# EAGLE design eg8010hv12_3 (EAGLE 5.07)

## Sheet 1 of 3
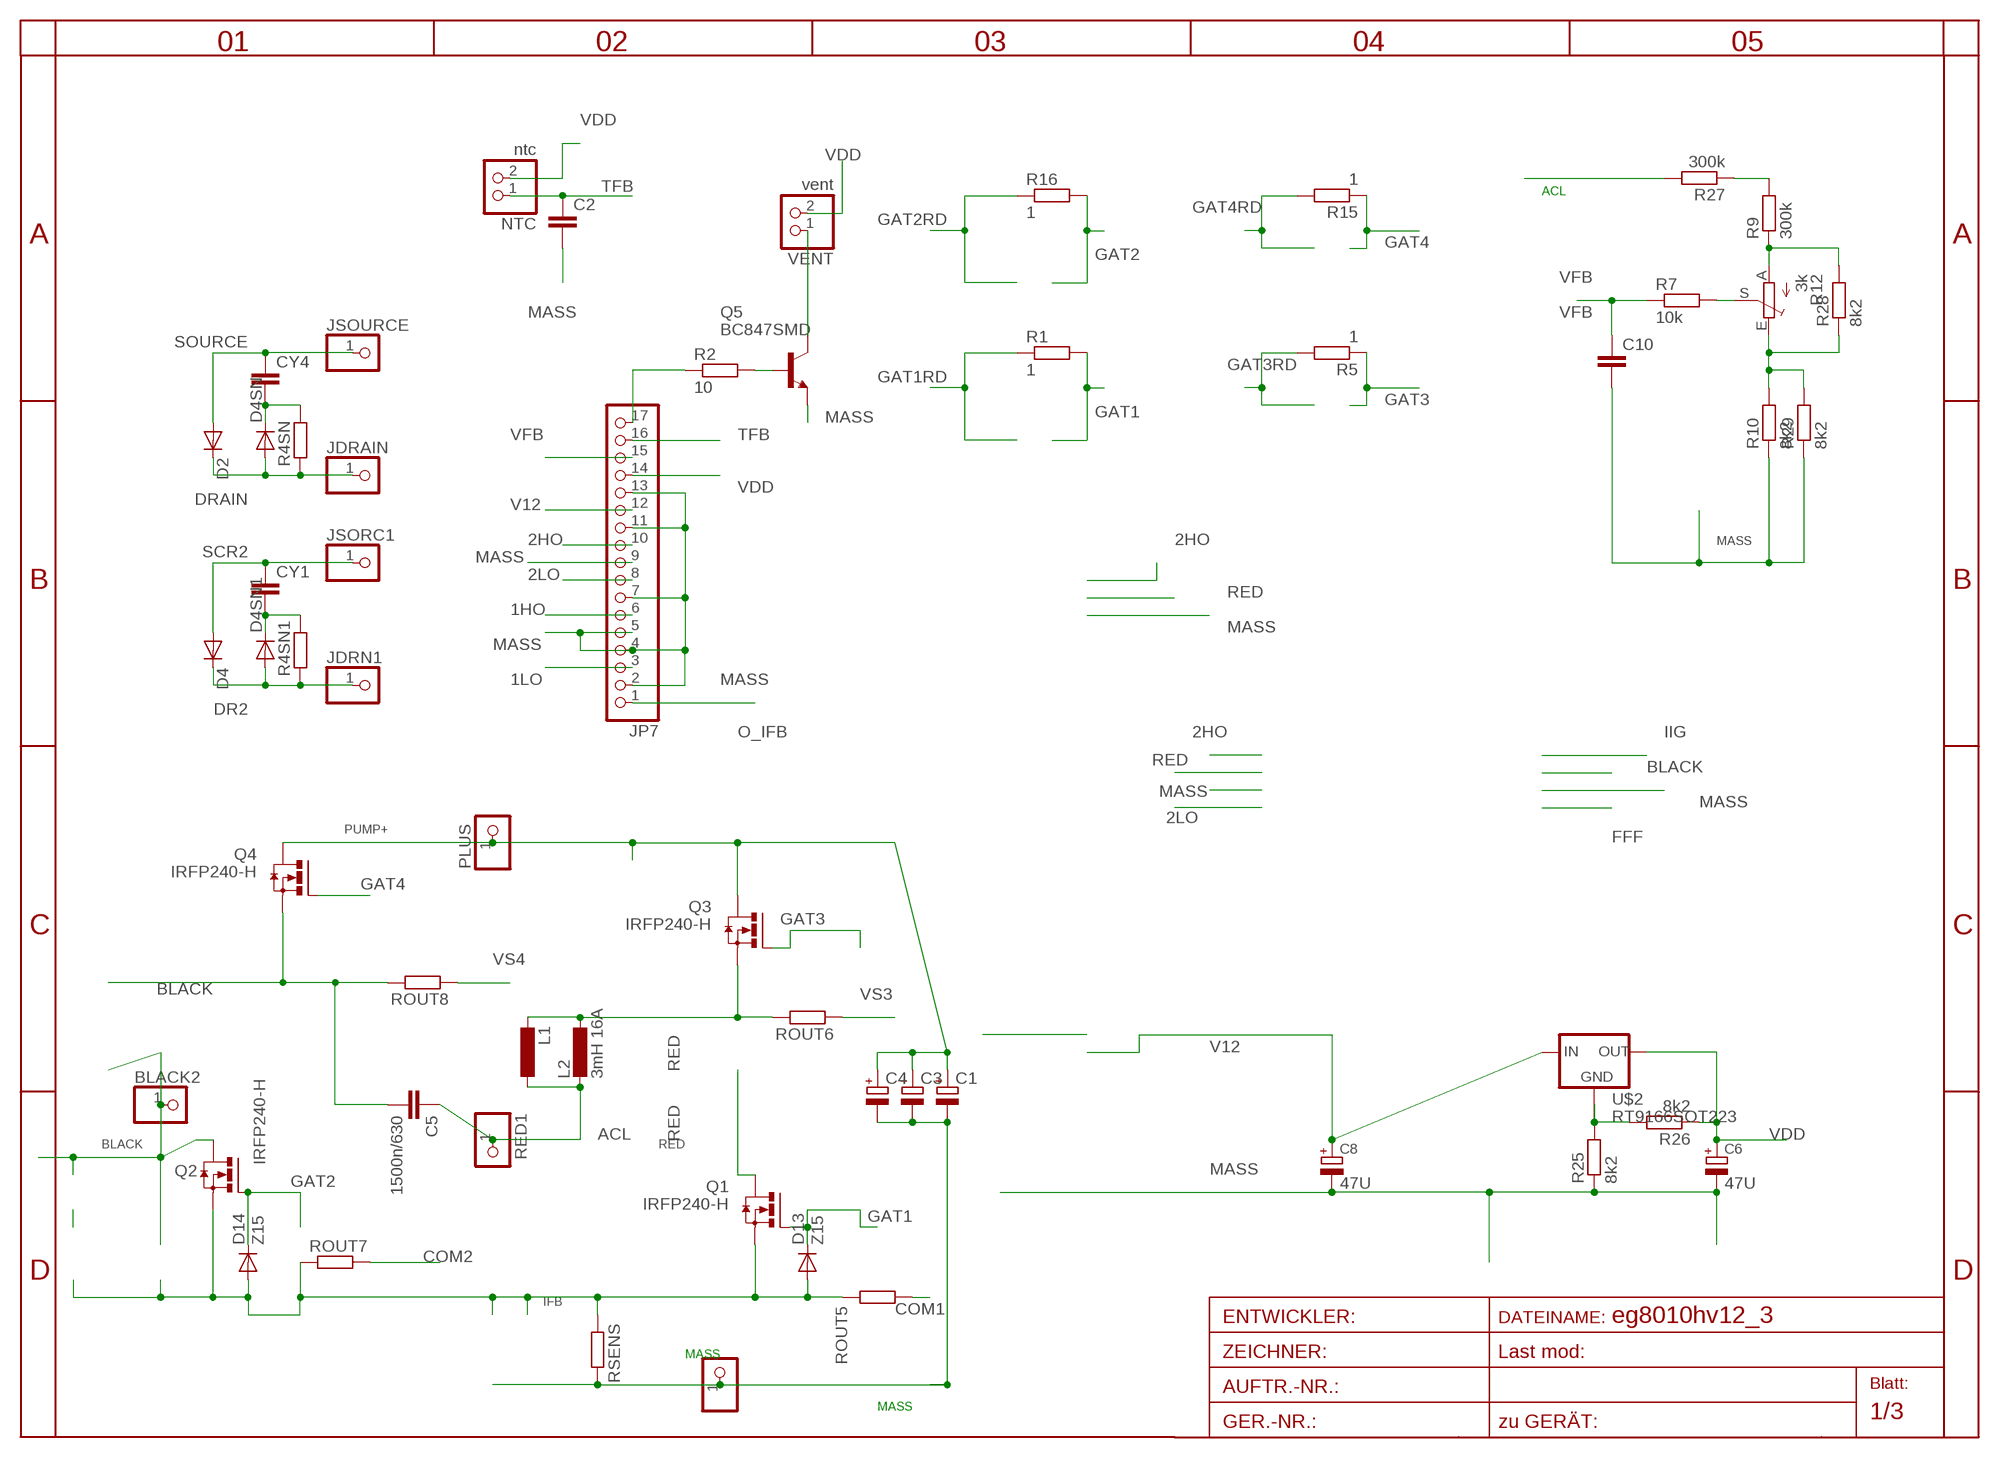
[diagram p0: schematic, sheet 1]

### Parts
BLACK2  PINHD-1X12MM3  [1X2MM3]
C1  CPOL-EUE5-13  [E5-13]
C2  C-EUC1206  [C1206]
C3  CPOL-EUE5-13  [E5-13]
C4  CPOL-EUE5-13  [E5-13]
C5  1500n/630  C-EU275-173X316  [C275-173X316]
C6  47U  CPOL-EUSMCA  [SMC_A]
C8  47U  CPOL-EUSMCA  [SMC_A]
C10  C-EUC0805  [C0805]
CY1  CXXC10B5  [XC10B5]
CY4  CXXC10B5  [XC10B5]
D2  DIODE-SMC  [SMC]
D4  DIODE-SMC  [SMC]
D4SN  DIODE-P1-10  [P1-10]
D4SN1  DIODE-P1-10  [P1-10]
D13  Z15  DIODE-MINIMELF  [MINIMELF]
D14  Z15  DIODE-MINIMELF  [MINIMELF]
JDRAIN  PINHD-1X11MM0  [1X1MM0]
JDRN1  PINHD-1X11MM0  [1X1MM0]
JP7  PINHD-1X17  [1X17]
JSORC1  PINHD-1X11MM0  [1X1MM0]
JSOURCE  PINHD-1X11MM0  [1X1MM0]
L1  L-EU4.13  [0204/13]
L2  3mH 16A  L-EURNG  [RING]
MINUS  PINHD-1X12MM3  [1X2MM3]
NTC  ntc  PINHD-1X2STR  [1X02]
PLUS  PINHD-1X12MM3  [1X2MM3]
Q1  IRFP240-H  [TO247BH]
Q2  IRFP240-H  [TO247BH]
Q3  IRFP240-H  [TO247BH]
Q4  IRFP240-H  [TO247BH]
Q5  BC847SMD  [SOT23]
R1  1  R-EU_R2512  [R2512]
R2  10  R-EU_R0805  [R0805]
R4SN  R-EU_0207/10  [0207/10]
R4SN1  R-EU_0207/10  [0207/10]
R5  1  R-EU_R2512  [R2512]
R7  10k  R-EU_R0805  [R0805]
R9  300k  R-EU_R1206  [R1206]
R10  8k2  R-EU_R0805  [R0805]
R12  3k  TRIM_EU-B64Y  [B64Y]
R15  1  R-EU_R2512  [R2512]
R16  1  R-EU_R2512  [R2512]
R25  8k2  R-EU_R0805  [R0805]
R26  8k2  R-EU_R0805  [R0805]
R27  300k  R-EU_R1206  [R1206]
R28  8k2  R-EU_R1206  [R1206]
R29  8k2  R-EU_R0805  [R0805]
RED1  PINHD-1X12MM3  [1X2MM3]
ROUT5  R-EU_R2512  [R2512]
ROUT6  R-EU_R2512  [R2512]
ROUT7  R-EU_R2512  [R2512]
ROUT8  R-EU_R2512  [R2512]
RSENS  R-EU_WIRE  [WIRE]
U$2  RT9166SOT223  [SOT223]
VENT  vent  PINHD-1X2STR  [1X02]

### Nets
1HO: JP7.6 ; also sheet 3
1LO: JP7.3 ; also sheet 3
2HO: JP7.10 ; also sheet 3
2LO: JP7.8 ; also sheet 3
ACL: C5.1 L1.1 L2.2 R27.2 RED1.1
BLACK: BLACK2.1 C5.2 Q2.D Q4.S ROUT8.2
COM1: ROUT5.1 ; also sheet 3
COM2: ROUT7.2 ; also sheet 3
DR2: D4.C D4SN1.A JDRN1.1 R4SN1.1
DRAIN: D2.C D4SN.A JDRAIN.1 R4SN.1
GAT1: D13.C Q1.G R1.2
GAT1RD: R1.1 ; also sheet 3
GAT2: D14.C Q2.G R16.2
GAT2RD: R16.1 ; also sheet 3
GAT3: Q3.G R5.1
GAT3RD: R5.2 ; also sheet 3
GAT4: Q4.G R15.1
GAT4RD: R15.2 ; also sheet 3
IFB: D13.A D14.A Q1.S Q2.S ROUT5.2 ROUT7.1 RSENS.1 ; also sheet 3
MASS: C1.- C2.2 C3.- C4.- C6.- C8.- C10.2 JP7.2 JP7.4 JP7.5 JP7.7 JP7.9 JP7.11 JP7.13 MINUS.1 Q5.2(E) R10.1 R25.1 R29.1 RSENS.2 ; also sheet 2,3
N$1: Q5.3(C) VENT.1
N$2: Q5.1(B) R2.2
N$3: JP7.17 R2.1
N$23: R9.2 R27.1
N$29: R10.2 R12.E R28.1 R29.2
N$30: R9.1 R12.A R28.2
N$31: R7.2 R12.S
O_IFB: JP7.1 ; also sheet 3
PUMP+: C1.+ C3.+ C4.+ PLUS.1 Q3.D Q4.D ; also sheet 2
RED: L1.2 L2.1 Q1.D Q3.S ROUT6.2
SCR2: CY1.1 D4.A JSORC1.1
SNUB1: CY1.2 D4SN1.C R4SN1.2
SNUB2: CY4.2 D4SN.C R4SN.2
SOURCE: CY4.1 D2.A JSOURCE.1
TFB: C2.1 JP7.16 NTC.1
V12: C8.+ JP7.12 U$2.3(IN) ; also sheet 2,3
VDD: C6.+ JP7.14 NTC.2 R26.1 U$2.1(OUT) VENT.2
VFB: C10.1 JP7.15 R7.1
VREGM: R25.2 R26.2 U$2.2(GND) U$2.4(GND1)
VS3: ROUT6.1 ; also sheet 3
VS4: ROUT8.1 ; also sheet 3

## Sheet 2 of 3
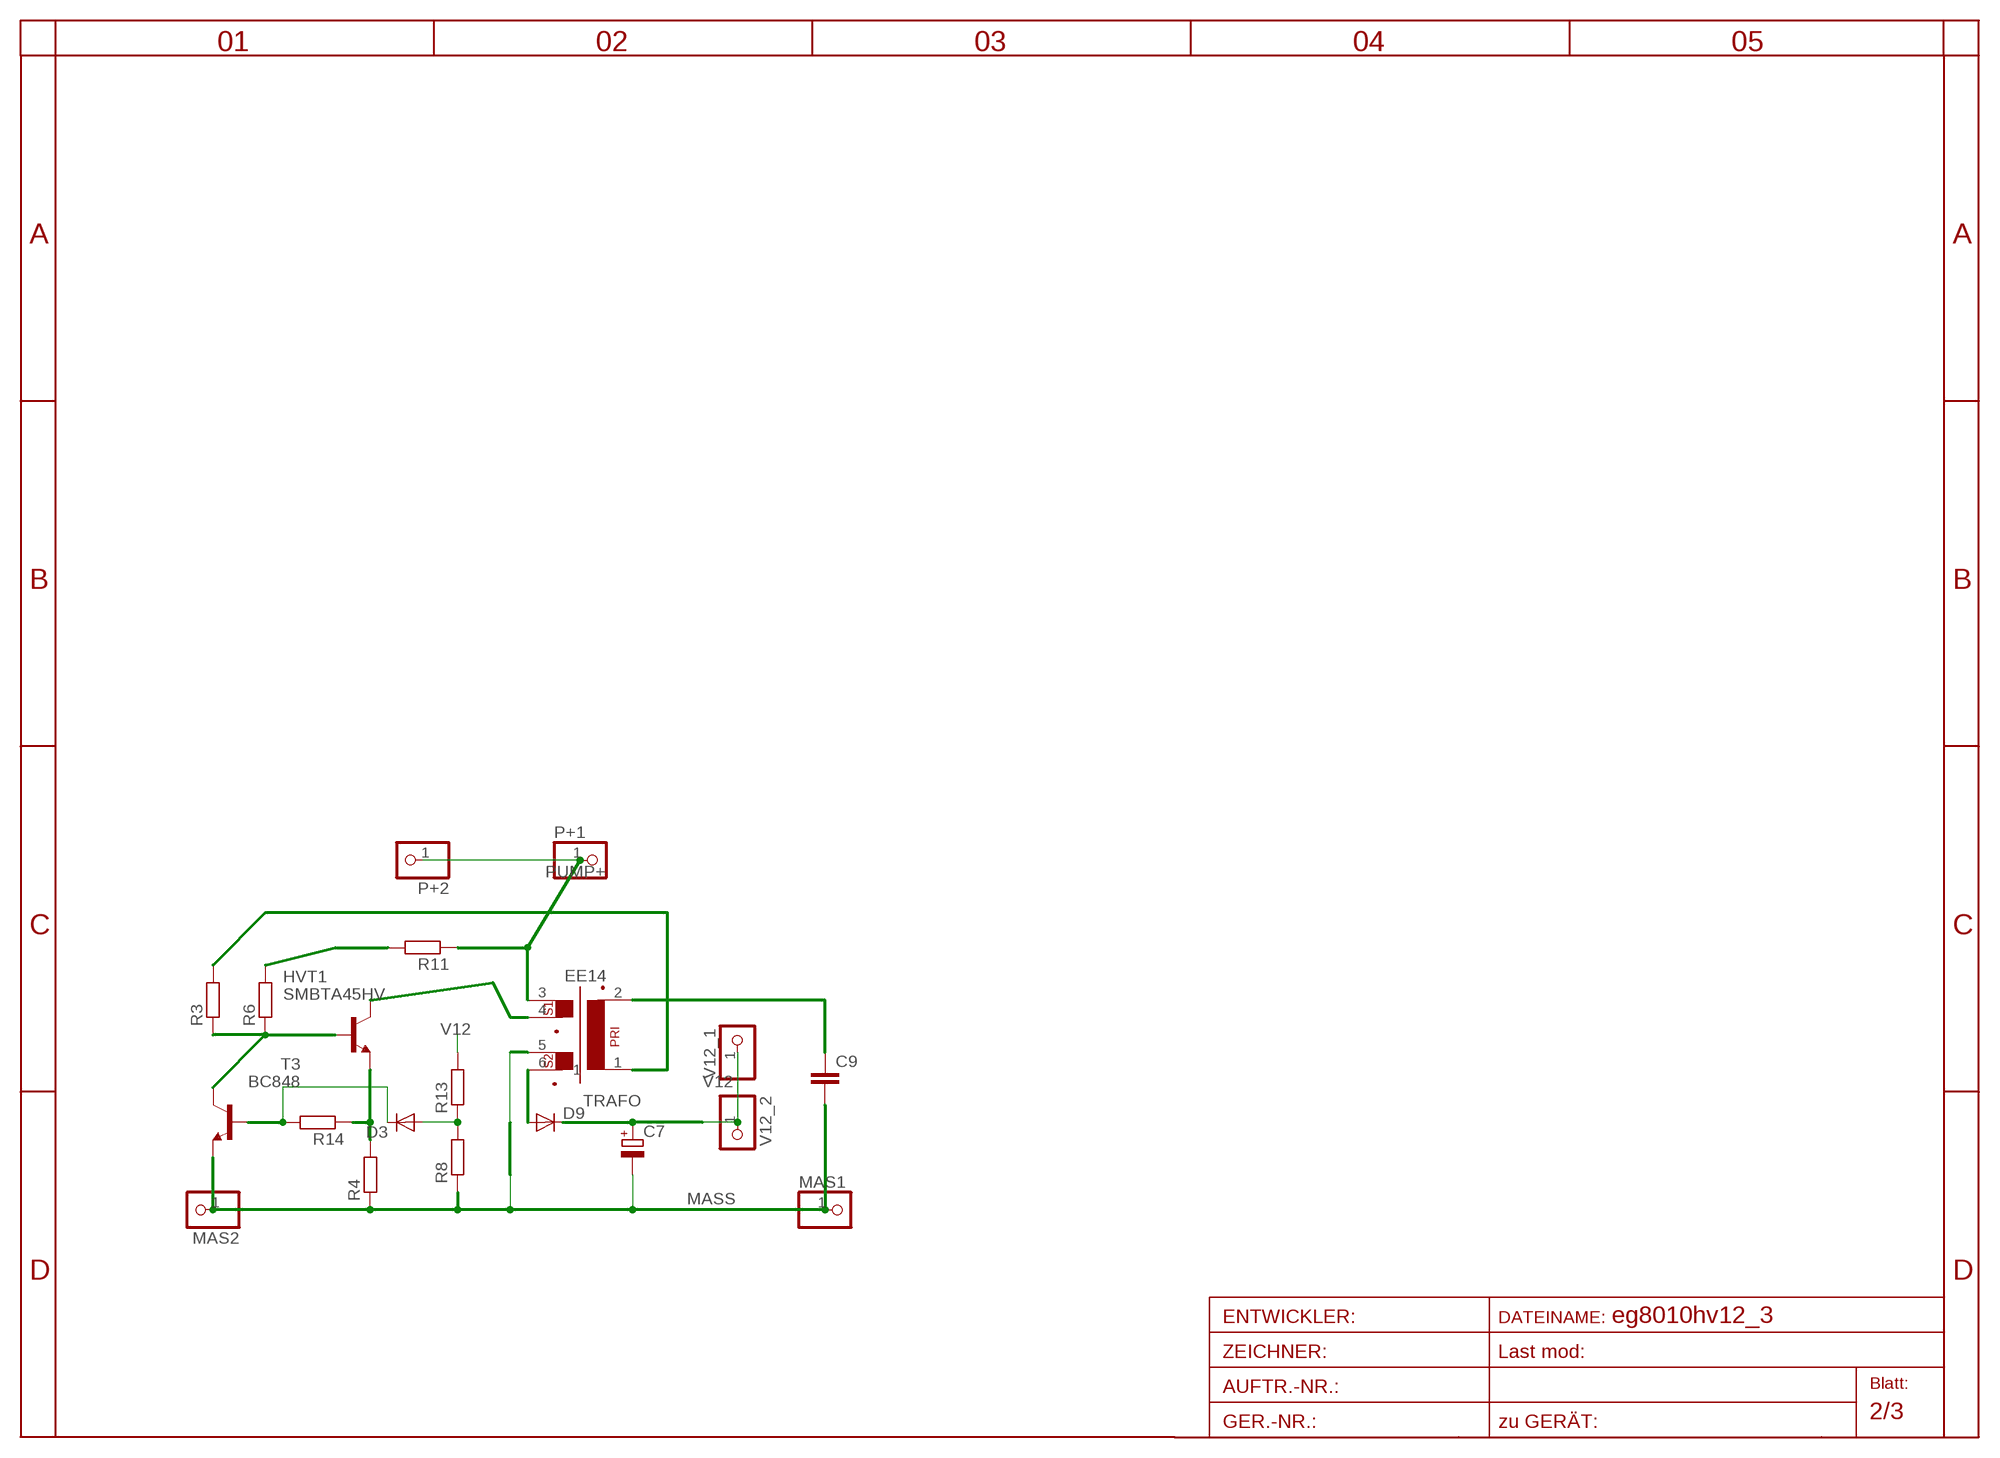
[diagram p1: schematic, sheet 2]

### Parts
C7  CPOL-EUSMCA  [SMC_A]
C9  C-EUC0805  [C0805]
D3  DIODE-MINIMELF  [MINIMELF]
D9  DIODE-SMA-DO214  [SMA-DO214AC]
HVT1  SMBTA45HV  [SOT23HV]
MAS1  PINHD-1X11X0.4  [1X01]
MAS2  PINHD-1X11X0.4  [1X01]
P+1  PINHD-1X11X0.4  [1X01]
P+2  PINHD-1X11X0.4  [1X01]
R3  R-EU_R0805  [R0805]
R4  R-EU_R0805  [R0805]
R6  R-EU_R1206  [R1206]
R8  R-EU_R0805  [R0805]
R11  R-EU_R1206  [R1206]
R13  R-EU_R0805  [R0805]
R14  R-EU_R0805  [R0805]
T3  BC848  [SOT23]
TRAFO  EE14  [EE14]
V12_1  PINHD-1X11X0.4  [1X01]
V12_2  PINHD-1X11X0.4  [1X01]

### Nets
A: D9.A TRAFO.6
B1C2: HVT1.1(B) R3.1 R6.1 T3.C
BT1: D3.C R14.2 T3.B
C1: HVT1.3(C) TRAFO.4
EB: HVT1.2(E) R4.2 R14.1
MASS: C7.- C9.2 MAS1.1 MAS2.1 R4.1 R8.1 T3.E TRAFO.5 ; also sheet 1,3
N$6: R3.2 TRAFO.1
N$7: C9.1 TRAFO.2
N$8: R6.2 R11.2
N$10: D3.A R8.2 R13.1
PUMP+: P+1.1 P+2.1 R11.1 TRAFO.3 ; also sheet 1
V12: C7.+ D9.K(C) R13.2 V12_1.1 V12_2.1 ; also sheet 1,3

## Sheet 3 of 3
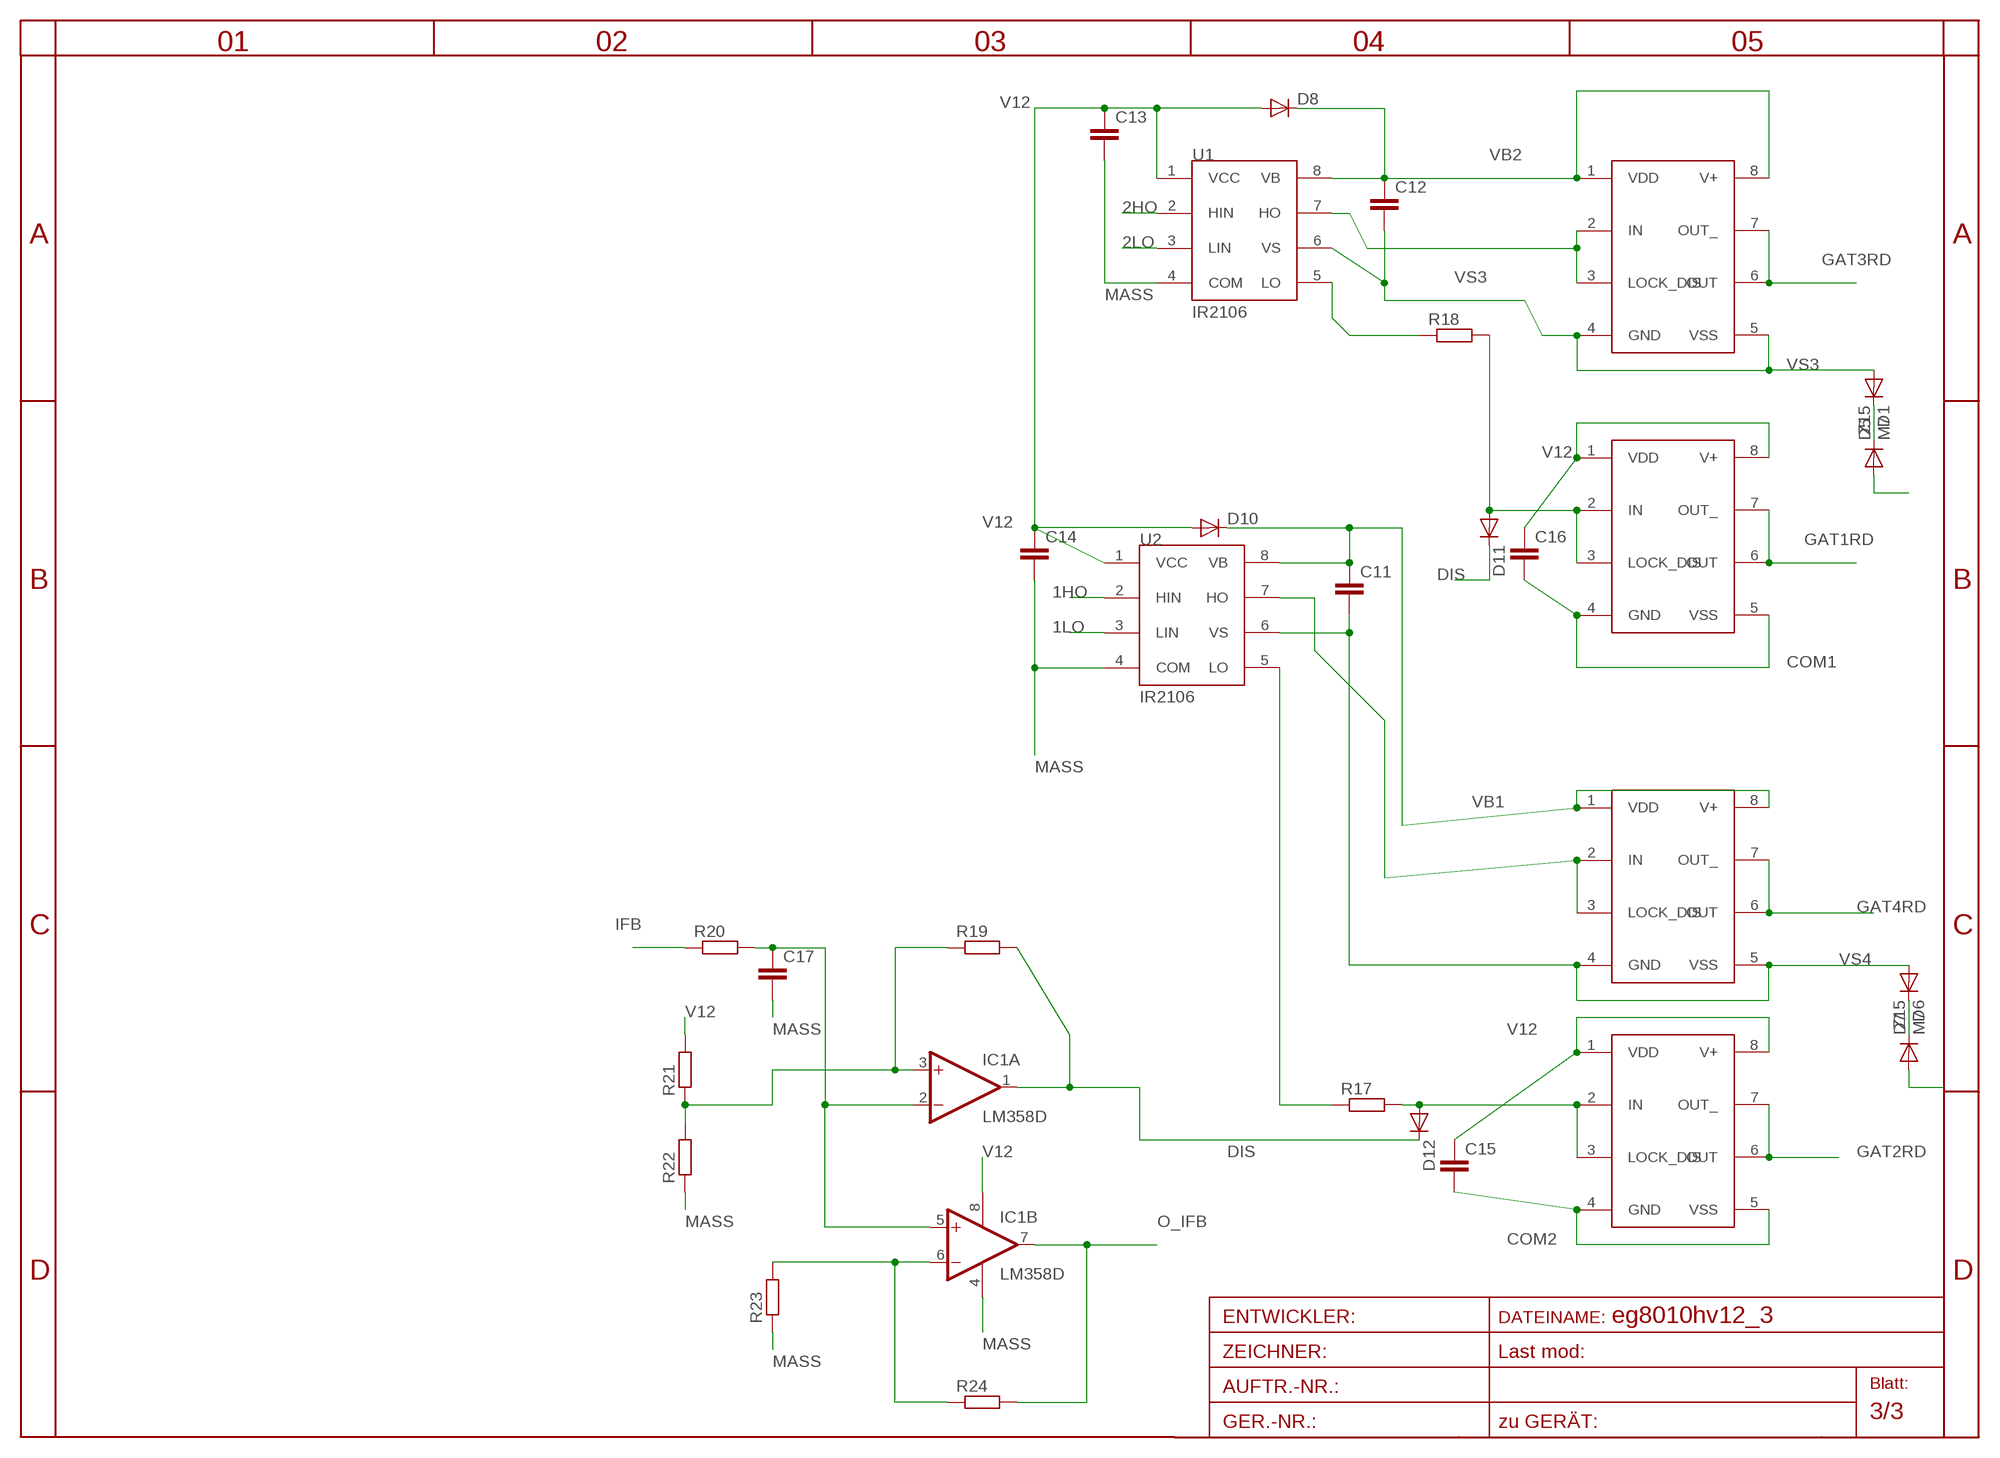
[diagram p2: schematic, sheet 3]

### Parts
1HDRV  TC4432X  [SO-08]
1LODRV  TC4432X  [SO-08]
2HDRV  TC4432X  [SO-08]
2LODRV  TC4432X  [SO-08]
C11  C-EUC058MLCC  [C058-020X040]
C12  C-EUC058MLCC  [C058-020X040]
C13  C-EUC1206  [C1206]
C14  C-EUC1206  [C1206]
C15  C-EUC1206  [C1206]
C16  C-EUC1206  [C1206]
C17  C-EUC1206  [C1206]
D1  Z15  DIODE-MINIMELF  [MINIMELF]
D5  M7  DIODE-SMA-DO214  [SMA-DO214AC]
D6  Z15  DIODE-MINIMELF  [MINIMELF]
D7  M7  DIODE-SMA-DO214  [SMA-DO214AC]
D8  DIODE-SMA-DO214  [SMA-DO214AC]
D10  DIODE-SMA-DO214  [SMA-DO214AC]
D11  DIODE-MINIMELF  [MINIMELF]
D12  DIODE-MINIMELF  [MINIMELF]
IC1  LM358D  [SO08]
R17  R-EU_0617/17  [0617/17]
R18  R-EU_0204/5  [0204/5]
R19  R-EU_R1206  [R1206]
R20  R-EU_R0805  [R0805]
R21  R-EU_R0805  [R0805]
R22  R-EU_R0805  [R0805]
R23  R-EU_R0805  [R0805]
R24  R-EU_R0805  [R0805]
U1  IR2106  [SO8-5]
U2  IR2106  [SO8-5]

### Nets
1HO: U2.2(HIN) ; also sheet 1
1LO: U2.3(LIN) ; also sheet 1
2HO: U1.2(HIN) ; also sheet 1
2LO: U1.3(LIN) ; also sheet 1
COM1: 2LODRV.4(GND) 2LODRV.5(VSS) C16.2 ; also sheet 1
COM2: 1LODRV.4(GND) 1LODRV.5(VSS) C15.2 ; also sheet 1
DIS: D11.C D12.C IC1.1(A:OUT) R19.2
GAT1RD: 2LODRV.6(OUT) 2LODRV.7(OUT_) ; also sheet 1
GAT2RD: 1LODRV.6(OUT) 1LODRV.7(OUT_) ; also sheet 1
GAT3RD: 2HDRV.6(OUT) 2HDRV.7(OUT_) ; also sheet 1
GAT4RD: 1HDRV.6(OUT) 1HDRV.7(OUT_) ; also sheet 1
IFB: R20.1 ; also sheet 1
MASS: C13.2 C14.2 C17.2 D5.A D7.A IC1.4(P:V-) R22.1 R23.1 U1.4(COM) U2.4(COM) ; also sheet 1,2
N$4: R18.1 U1.5(LO)
N$5: 1LODRV.2(IN) 1LODRV.3(LOCK_DIS) D12.A R17.2
N$9: IC1.3(A:+IN) R19.1 R21.1 R22.2
N$11: R17.1 U2.5(LO)
N$12: 2HDRV.2(IN) 2HDRV.3(LOCK_DIS) U1.7(HO)
N$13: 1HDRV.2(IN) 1HDRV.3(LOCK_DIS) U2.7(HO)
N$15: C17.1 IC1.2(A:-IN) IC1.5(B:+IN) R20.2
N$16: 2LODRV.2(IN) 2LODRV.3(LOCK_DIS) D11.A R18.2
N$18: IC1.6(B:-IN) R23.2 R24.1
N$20: D1.C D5.K(C)
N$24: D6.C D7.K(C)
O_IFB: IC1.7(B:OUT) R24.2 ; also sheet 1
V12: 1LODRV.1(VDD) 1LODRV.8(V+) 2LODRV.1(VDD) 2LODRV.8(V+) C13.1 C14.1 C15.1 C16.1 D8.A D10.A IC1.8(P:V+) R21.2 U1.1(VCC) U2.1(VCC) ; also sheet 1,2
VB1: 1HDRV.1(VDD) 1HDRV.8(V+) C11.1 D10.K(C) U2.8(VB)
VB2: 2HDRV.1(VDD) 2HDRV.8(V+) C12.1 D8.K(C) U1.8(VB)
VS3: 2HDRV.4(GND) 2HDRV.5(VSS) C12.2 D1.A U1.6(VS) ; also sheet 1
VS4: 1HDRV.4(GND) 1HDRV.5(VSS) C11.2 D6.A U2.6(VS) ; also sheet 1

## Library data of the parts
1HDRV 1LODRV 2HDRV 2LODRV = microchip:TC4432
BLACK2 JDRAIN JDRN1 JSORC1 JSOURCE MAS1 MAS2 MINUS P+1 P+2 PLUS RED1 V12_1 V12_2 = pinhead:PINHD-1X1: PIN HEADER
C1 C3 C4 C6-C8 = rcl:CPOL-EU: POLARIZED CAPACITOR, European symbol
C2 C5 C9-C17 = rcl:C-EU: CAPACITOR, European symbol
CY1 CY4 = rcl:CX: X CAPACITOR
D1-D4 D4SN D4SN1 D5-D14 = diode:DIODE-: DIODE
HVT1 = transistor-npn:SMBTA45
IC1 = linear:LM358: OP AMP also LM158; LM258; LM2904 Source: http://cache.national.com/ds/LM/LM158.pdf
JP7 = pinhead:PINHD-1X17: PIN HEADER
L1 L2 = rcl:L-EU: INDUCTOR, European symbol
NTC VENT = pinhead:PINHD-1X2: PIN HEADER
Q1-Q4 = transistor-power:IRFP240: HEXFET Power MosFet Source: http://www.irf.com/
Q5 = transistor-npn:BC847*: NPN Transistor
R1-R4 R4SN R4SN1 R5 R6 R8 R11 R13-R16 R18-R24 ROUT5-ROUT8 RSENS = rcl:R-EU_: RESISTOR, European symbol
R7 R9 R10 R17 R25-R29 = rcl-2:R-EU_: RESISTOR, European symbol
R12 = pot:TRIM_EU-: POTENTIOMETER
T3 = transistor:BC848: NPN TRANSISTOR
TRAFO = trafo:EE14
U1 U2 = irf-2:IR2106
U$2 = v-reg:RT9166

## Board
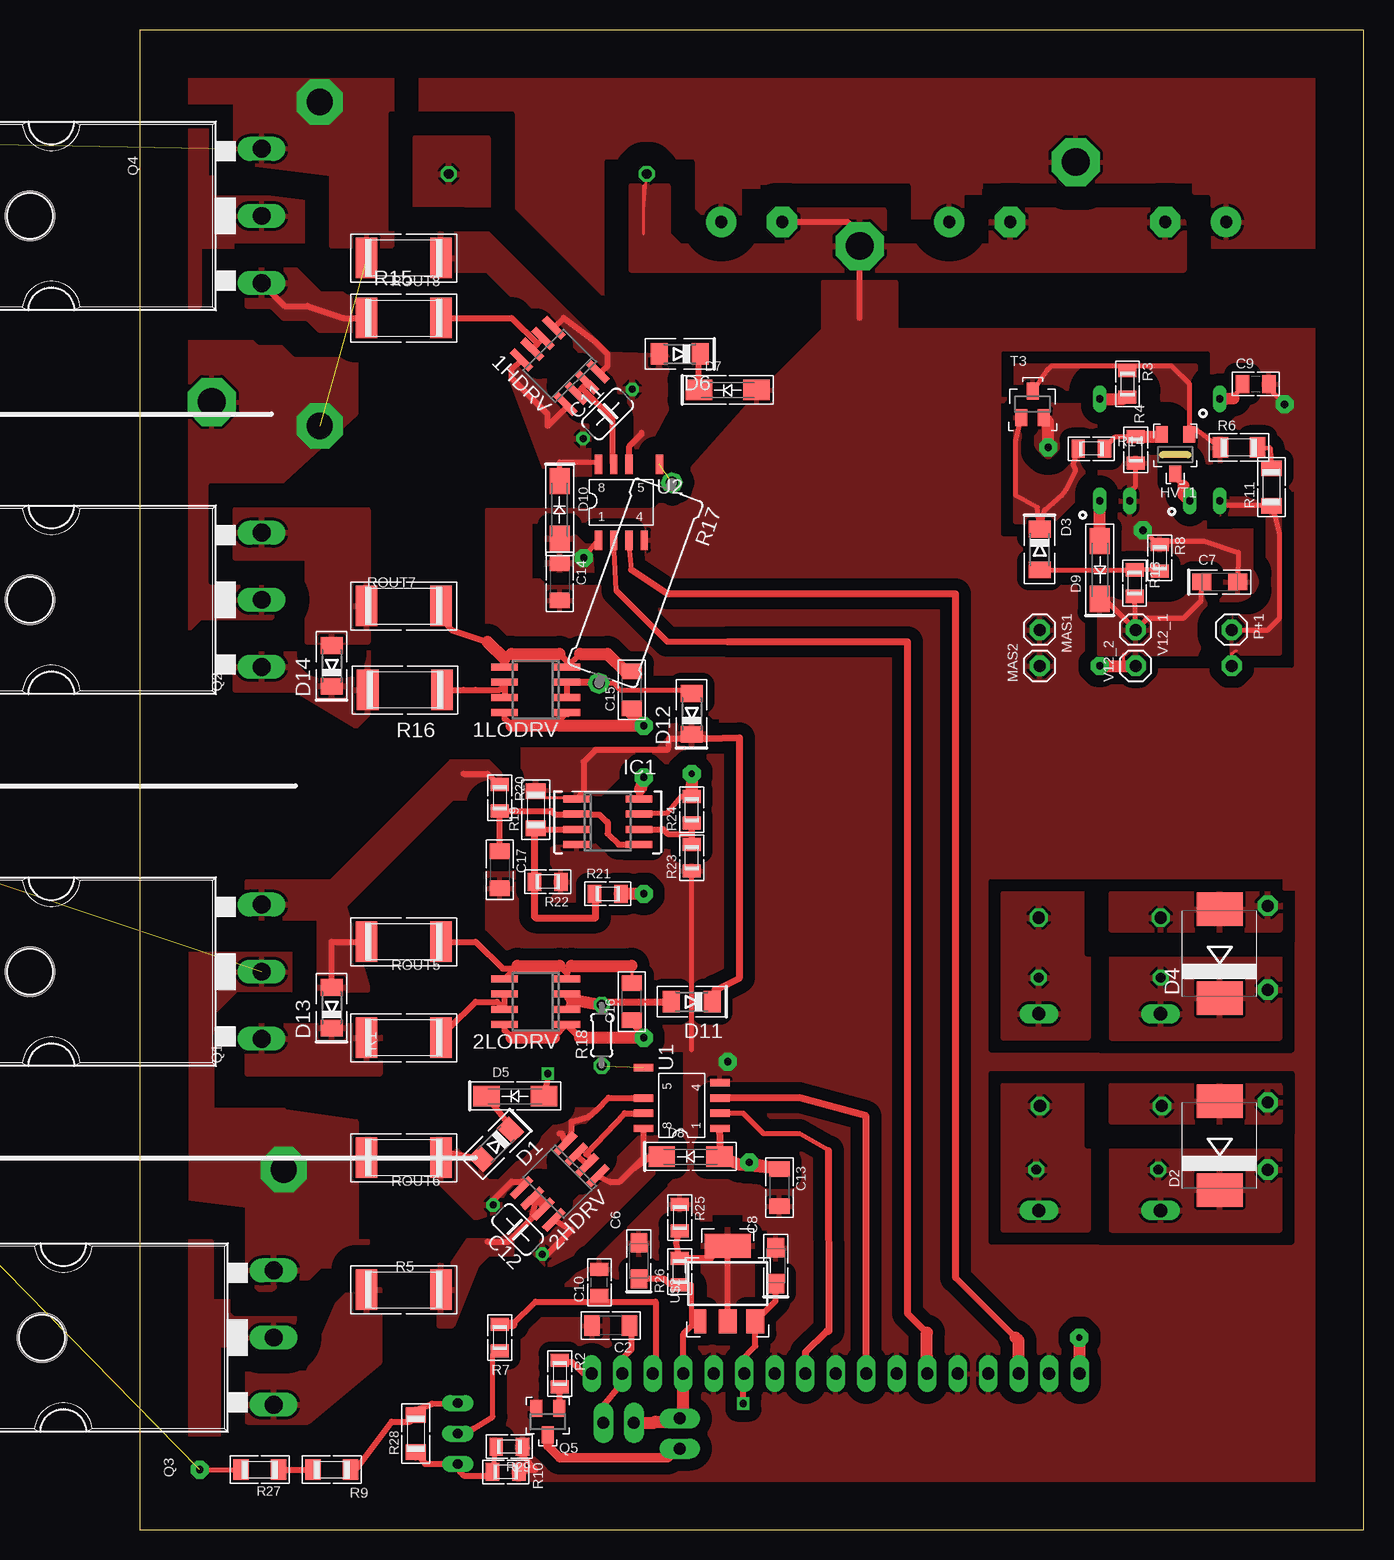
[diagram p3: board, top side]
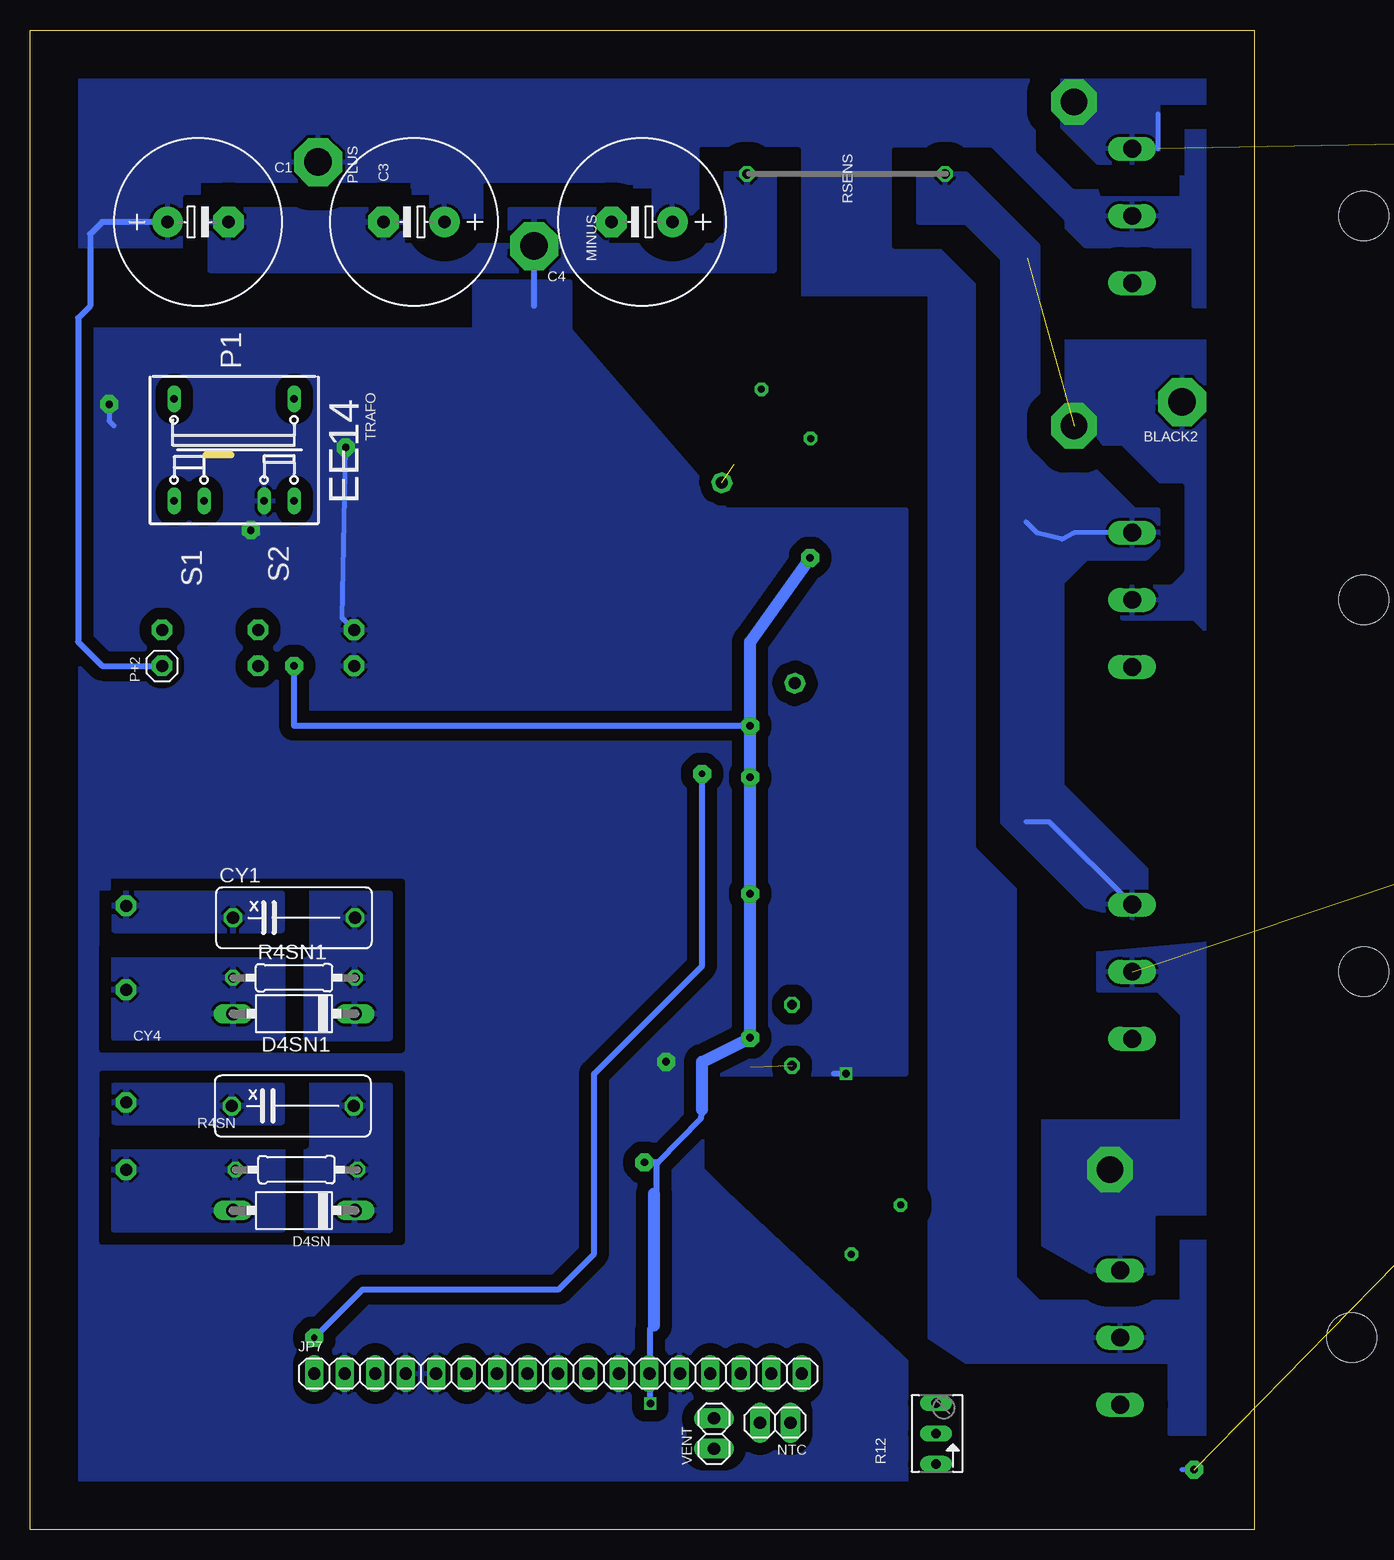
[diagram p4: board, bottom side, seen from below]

Size 102 x 125 mm. Coordinates in mm from the lower left corner, seen from the top.
Outline: 0,0 102,0 102,125 0,125 0,0
Copper layers (1*16): Top 0.035mm / dielectric 1.5mm / Bottom 0.035mm
Design rules "default *": minimum track width 10mil, minimum drill 20mil, track to track 8mil, track to pad 8mil, pad to pad 8mil, via to via 8mil, smd to smd 8mil, copper to edge 4mm, drill to drill 8mil, minimum pad ring 10mil, minimum via ring 8mil, stop-mask expansion 4mil, vias tented up to drill 0mil, thermal gap 10mil

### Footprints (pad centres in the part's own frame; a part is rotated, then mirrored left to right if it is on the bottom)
SO-08 = smd 0.6 x 2.2: 1 -1.905,-2.6; 2 -0.635,-2.6; 3 0.635,-2.6; 4 1.905,-2.6; 5 1.905,2.6; 6 0.635,2.6; 7 -0.635,2.6; 8 -1.905,2.6
1X2MM3 = drill 2.3 pad 4 octagon: 1 0,0
E5-13 = drill 1.016 pad 2.54 round: + -2.54,0 | drill 1.016 pad 2.54 octagon: - 2.54,0
C1206 = smd 1.3 x 1.7: 1 -1.55,0; 2 1.55,0
C275-173X316 = drill 1.194 octagon: 1 -13.716,0; 2 13.716,0
SMC_A = smd 1.6 x 1.4: + -1.5,0; - 1.5,0
C0805 = smd 1.1 x 1.5: 1 -1.1,0; 2 1.1,0
C058-020X040 = drill 0.6 octagon: 1 -2.9,0; 2 2.9,0
XC10B5 = drill 1.016 octagon: 1 -5.08,0; 2 5.08,0
MINIMELF = smd 1.4 x 1.8: A 1.7,0; C -1.7,0
SMC = smd 2.8 x 3.8: A 3.7,0; C -3.7,0
P1-10 = drill 1.118 long: A 5.08,0; C -5.08,0
SMA-DO214AC = smd 2.2 x 1.7: A 2.4,0; K -2.4,0
SOT23HV = smd 1 x 1.4: 1 -1.15,-1.7; 2 1.15,-1.7; 3 0,1.6
SO08 = smd 0.6 x 2.2: 1 -1.905,-2.6; 2 -0.635,-2.6; 3 0.635,-2.6; 4 1.905,-2.6; 5 1.905,2.6; 6 0.635,2.6; 7 -0.635,2.6; 8 -1.905,2.6
1X1MM0 = drill 1 pad 1.676 octagon: 1 0,0
1X17 = drill 1.016 long: 1 -20.32,0; 2 -17.78,0; 3 -15.24,0; 4 -12.7,0; 5 -10.16,0; 6 -7.62,0; 7 -5.08,0; 8 -2.54,0; 9 0,0; 10 2.54,0; 11 5.08,0; 12 7.62,0; 13 10.16,0; 14 12.7,0; 15 15.24,0; 16 17.78,0; 17 20.32,0
0204/13 = drill 0.813 octagon: 1 -6.872,0; 2 6.872,0
RING = drill 3 pad 4 round: 1 -3.15,0; 2 3.15,0
1X01 = drill 1 pad 1.676 octagon: 1 0,0
1X02 = drill 1.016 pad 1.676 long: 1 -1.27,0; 2 1.27,0
TO247BH = drill 1.499 long: D 0,-10.16; G -5.588,-10.16; S 5.588,-10.16 | hole 4.115: 0,9.144
SOT23 = smd 1 x 1.4: 1 -0.95,-1.1; 2 0.95,-1.1; 3 0,1.1
R2512 = smd 1.8 x 3.4: 1 -3.1,0; 2 3.1,0
R0805 = smd 1.1 x 1.5: 1 -1.1,0; 2 1.1,0
0207/10 = drill 0.813 octagon: 1 -5.08,0; 2 5.08,0
R1206 = smd 1.3 x 1.7: 1 -1.55,0; 2 1.55,0
B64Y = drill 0.813 long: A 2.54,0; E -2.54,0; S 0,0
0617/17 = drill 1 pad 1.676 octagon: 1 -8.89,0; 2 8.89,0
0204/5 = drill 0.813 octagon: 1 -2.54,0; 2 2.54,0
WIRE = drill 0.813 octagon: 1 -8.25,0; 2 8.25,0
SOT23' = smd 1 x 1.4: B -0.95,-1.1; C 0,1.1; E 0.95,-1.1
EE14 = drill 0.6 pad 1 long: 1 4.25,-5; 2 4.25,5; 3 -4.25,5 | drill 0.6 pad 1.016 long: 4 -4.25,2.5; 5 -4.25,-2.5; 6 -4.25,-5
SO8-5 = smd 0.61 x 1.626: 1 -1.27,-2.54; 2 0,-2.54; 3 1.27,-2.54; 4 2.54,-2.54; 5 3.81,3.81; 6 1.27,3.81; 7 0,3.81; 8 -1.27,3.81
SOT223 = smd 1 x 2: 1 -2.3,-3.15 | smd 1.5 x 2: 2 0,-3.15; 3 2.3,-3.15 | smd 3.8 x 2: 4 0,3.15

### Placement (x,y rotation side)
1HDRV  35,97 45 top
1LODRV  33,70 90 top
2HDRV  35,29 135 top
2LODRV  33,44 90 top
BLACK2  6,94 180 bottom
C1  88,109 0 bottom
C2  39.25,17 180 top
C3  70,109 180 bottom
C4  51,109 180 bottom
C5  not placed on the board
C6  41.6,22.4 90 top
C7  90,79 0 top
C8  53,22 90 top
C9  93,95.5 0 top
C10  38.3,20.6 90 top
C11  39,93 45 top
C12  31.5,25 135 top
C13  53.3,28.5 270 top
C14  35,79 270 top
C15  41,70 90 top
C16  41,44 90 top
C17  30,55 270 top
CY1  80,51 0 bottom
CY4  80.1,35.3 0 bottom
D1  29.7,32.1 225 top
D2  90,32 90 top
D3  75,81.7 270 top
D4  90,48 90 top
D4SN  80,26.6 180 bottom
D4SN1  80,43 180 bottom
D5  31.28,36.14 0 top
D6  45,98 180 top
D7  49,95 0 top
D8  45.9,31.1 0 top
D9  80,80 90 top
D10  35,85 270 top
D11  46,44 180 top
D12  46,68 90 top
D13  16,43.5 90 top
D14  16,72 90 top
HVT1  86.3,89.6 180 top
IC1  39,59 270 top
JDRAIN  94,30 270 top
JDRN1  94,45 0 top
JP7  58,13 0 bottom
JSORC1  94,52 0 top
JSOURCE  94,35.6 270 top
L1  not placed on the board
L2  not placed on the board
MAS1  75,75 270 top
MAS2  75,72 90 top
MINUS  60,107 270 bottom
NTC  39.9,8.9 180 bottom
P+1  91,75 270 top
P+2  91,72 90 bottom
PLUS  78,114 270 bottom
Q1  0,46.5 90 top
Q2  0,77.5 90 top
Q3  1,16 90 top
Q4  0,109.5 90 top
Q5  34,9 180 top
R1  22,41 180 top
R2  35,13 270 top
R3  82.3,95.5 270 top
R4  83,90 90 top
R4SN  79.8,30 0 bottom
R4SN1  80,46 0 bottom
R5  22,20 0 top
R6  91.6,90.2 0 top
R7  30,16 270 top
R8  85,81 270 top
R9  16,5 180 top
R10  30.5,4.8 180 top
R11  94.3,86.9 90 top
R12  26.5,8 90 bottom
R13  82.9,78.9 270 top
R14  79.3,90.1 180 top
R15  22,101 0 top
R16  22.1,70 180 top
R17  41.3,78.9 250 top
R18  38.5,41.2 90 top
R19  33,60 90 top
R20  30,61 270 top
R21  39,53 0 top
R22  34,54 180 top
R23  46,56 90 top
R24  46,60 90 top
R25  45,26 270 top
R26  45,21.5 90 top
R27  10,5 180 top
R28  23,8 90 top
R29  30.8,6.9 180 top
RED1  not placed on the board
ROUT5  22,49 180 top
ROUT6  22,31 180 top
ROUT7  22,77 0 top
ROUT8  22,106 180 top
RSENS  34,113 180 bottom
T3  BC848  [SOT23']  74.4,93.8 0 top
TRAFO  85,90 90 bottom
U1  45.8,34.7 90 top
U2  39.5,85 0 top
U$2  49,20.5 0 top
V12_1  83,75 270 top
V12_2  83,72 90 top
VENT  45,8 90 bottom

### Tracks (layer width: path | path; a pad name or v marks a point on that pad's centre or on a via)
1HO
  Top 0.406: 39.73,78.27 U2.2
  Top 0.5: 39.73,78.27 44,74 49,74
  Top 0.6: 65.6,16.4 64,18 64,74 49,74
  Top 1: 65.6,16.4 65.6,14.4 JP7.6
1LO
  Top 0.406: 41,80 U2.3
  Top 0.5: 73,16 68,21
  Top 0.6: 68,21 68,78 44,78 41,80
  Top 1: JP7.3 73.24,15.76 73,16
2HO
  Top 0.406: U1.2 50.3,34.7 52,33 55,33 57.4,31.6
  Top 0.6: 57.4,31.6 57.46,16.54 57.24,16.54 55.5,14.8 JP7.10
2LO
  Top 0.6: U1.3 55,36 60.54,34.46 JP7.8
A
  Top 1: D9.A TRAFO.6
ACL  (via drill 0.6 pad 1.5)  (4 unrouted)
  Top 0.406: v5,5 R27.2
  Bottom 0.406: v5,5 6,5
B1C2
  Top 0.406: R6.1 88.05,91.7 HVT1.1 87.45,95.55 86,97 82.9,97 | 82.7,97 R3.1 82.9,97 | T3.C 75.6,96.6 76,97 82.7,97 | 82.9,97 82.7,97
  pour Top (isolate 2): 88,92 88,97 73,97 73,94 86,94 86,92 89,89 91,89 91,91
BLACK  (via drill 2.2 pad 3.81)  (2 unrouted)
  Bottom 0.406: Q4.S 8,115.09 8,118
  other vias: 15,92 15,119
  pour Bottom (isolate 2, rank 2): 16,117 13,114 8,114 8,119 -19,119 -19,99 19,99 6,82 8,79 11,79 11,76 5,76 4,75 4,70 -24,70 -24,121 16,121
  pour Top (isolate 2, rank 3): 21,121 21,107 16,107 16,113 8,114 8,119 -19,119 -19,99 18,99 18,93 6,82 6,79 11,79 11,76 5,76 4,75 4,70 -23,70 -23,99 -31,107 -45,107 -45,121
BT1
  Top 0.406: T3.B 73,90.75 73,86.2 74.8,85.2 D3.C 75.4,85 76.9,86.3 77.2,86.7 78,88.3 77.8,88.8 R14.2
  pour Top (isolate 1.5, rank 2): 80,90 80,88 76,84 73,84 73,93 75,93 75,92 77,90
C1
  Top 0.406: HVT1.3 86.3,87.7 87,87
  Top 1: 87,87 87,86.25 TRAFO.4
COM1
  Top 0.254: 41,47 C16.2 | 2LODRV.4 36,47
  Top 0.5: 2LODRV.4 35.6,46.4 35,47 | 31.25,46.75 2LODRV.5 | 31.25,46.75 31.5,47 | ROUT5.1 28,49 30.25,46.75 31.25,46.75
  Top 1: 36,47 41,47 | 31.5,47 35,47
COM2
  Top 0.5: 31,73 30.4,72.4 1LODRV.5 30.4,72.6 | 35,73 36,72 35.69,72 1LODRV.4 36.69,73 | 40.45,71.55 C15.2 | 29,74 26,75 25.81,75.19 ROUT7.2
  Top 1: 31,73 35,73 | 40.45,71.55 39,73 36.69,73 | 29,74 30.4,72.6
DIS
  Top 0.254: R19.2 33,61 36,61 IC1.1
  Top 0.5: 48,45 47.9,45 D11.C | 47.1,65.9 44.1,65.9 44,65 38,65 37,64 37,61.51 IC1.1
  Top 0.6: 48,45 50,46 50,66 47.1,65.9 D12.C
  pour Top (isolate 1.27, rank 2): 32,67 47,67 47,63 40,63 38,61 32,61 32,66
DR2
  pour Top (isolate 2, rank 2): 95,48 81,48 81,41 95,41
  pour Bottom (isolate 2, rank 2): 95,48 81,48 81,41 95,41
DRAIN
  pour Top (isolate 2, rank 2): 95,32 81,32 81,25 95,25
  pour Bottom (isolate 2, rank 2): 95,32 81,32 81,25 95,25
EB
  Top 0.406: R14.1 81.3,91.1 R4.2 | 84.95,91.1 HVT1.2
  Top 1: R4.2 84.95,91.1
GAT1
  pour Top (isolate 2): 9,42 20,42 20,38 9,38
GAT1RD
  Top 0.5: 2LODRV.6 2LODRV.7 29.77,44 28,44 25.81,41.81 R1.1
GAT2
  pour Top (isolate 2, rank 2): 8,73 14,73 16,76 19,76 19,68 18,67 13,70 8,70
GAT2RD
  Top 0.5: 1LODRV.7 1LODRV.6 30.4,70.4 30,70 28,70 27,70 R16.1
GAT3
  pour Top (isolate 2, rank 3): 9,13 9,9 14,9 20,14 20,20 17,20 14,13
GAT3RD
  Top 0.5: 29,24 30.7,24 32.7,26 33,27.4 2HDRV.6 33.82,27 34,27 33,27.82 2HDRV.7
  pour Top (isolate 1.5, rank 2): 28,25 35,28 32,23 29,23 28,22 26,17 25,17 25,22 26,22
GAT4
  Top 0.5: Q4.G 12.07,102 14,102 17,101 R15.1
  pour Top (isolate 1.5): 9,105 13,105 15,103 18,103 19,102 19,101 18,100 15,100 14,101 12,101 11,102 9,102
GAT4RD
  Top 0.5: 33.16,98.84 1HDRV.7 | 33.16,98.84 1HDRV.6 | R15.2 31,101 33.16,98.84 | 33.16,98.84
IFB
  Top 0.5: R20.1 29.9,62.1 29,63 27,63 | ROUT5.2 16,49 D13.A
  Bottom 0.406: Q1.S 17.07,59 19,59 | 19,84 18.08,83.08 16,82.55 14.99,83.09 Q2.S
  pour Bottom (isolate 2): 28,113 28,109 24,109 21,106 21,59 14,52 10,51 9,52 9,55 16,62 16,79 14,81 9,81 8,82 8,85 10,85 18,93 18,107 24,113
  pour Top (isolate 2, rank 2): 23,116 29,116 29,109 23,109
  pour Top (isolate 2, rank 2): 9,51 9,54 16,54 26,64 29,64 30,63 30,61 26,61 17,52 19,45 15,45 15,51
  pour Top (isolate 2, rank 2): 8,85 19,85 19,74 14,74 14,81 8,81
MASS  (via drill 0.6, 0.6 pad 1.5)
  Top 0.254: 42,110 42,112 | C4.- 53,109 | 42,108 42,110 | 42,110 RSENS.2
  Top 0.4: 46,40 R23.1
  Top 0.406: C7.- 91.55,81.45 88.7,82.4 85.8,82.4 R8.1 84.9,82.1 v83.6,83.3 | C9.2 94.1,95.1 v95.4,93.8 | TRAFO.5 82.5,86.5 83,87 R4.1
  Top 0.5: C4.- 59,109 60,108 60,101 | D5.A 34,37.4 v34,38 | R29.1 31.9,6.1 33,5 31.8,5 R10.1
  Top 1: v75.7,90.2 75.7,92.35 T3.E
  Bottom 0.406: v75.7,90.2 76,76 MAS1.1 | v95.4,93.8 95.4,92.4 95,92 | 83,83 v83.6,83.3
  Bottom 0.5: 60,102 MINUS.1 | v34,38 35,38
  other vias: 49,39
  pour Bottom (isolate 2): 96,97 96,73 73,73 73,97
  pour Top (isolate 2, rank 5): 96,97 96,73 73,73 73,97
  pour Bottom (isolate 1, rank 4): 44,85 57,100 57,104 65,104 65,100 105,100 105,4 29,4 29,14 44,28 46,30 46,38 29,38 29,85
  pour Top (isolate 1, rank 4): 51,94 57,100 57,104 63,104 63,100 100,100 100,4 29,4 30,15 45.5,30 45.5,40 29,40 29,85 43,85
  pour Bottom (isolate 2, rank 2): 40,113 44,113 44,108 45,107 54,107 54,110 62,110 62,107 71,107 71,110 86,110 87,109 87,105 40,105
  pour Top (isolate 2, rank 2): 41,112 44,112 44,108 45,107 54,107 54,110 62,110 62,107 71,107 71,110 86,110 87,109 87,105 41,105
N$1
  Top 0.8: VENT.1 44.73,6.73 44,6 35,6 34,7 34,8 34.1,7 Q5.3
N$2
  Top 0.5: R2.2 35,10.15 Q5.1
N$3
  Top 0.5: JP7.17 37,13 36,14 35.1,14 R2.1
N$4  (1 unrouted)
N$5
  Top 0.4: R17.2 39.45,70.55 40,70 45.7,70 D12.A
  Top 0.5: 1LODRV.3 1LODRV.2
  Top 0.6: R17.2 37.59,70.64 1LODRV.3
N$6
  Top 0.406: 81.95,94.25 R3.2
  Top 1: TRAFO.1 81.95,94.25
N$7
  Top 0.406: 91.15,94.3 C9.1
  Top 1: TRAFO.2 91.15,94.3
N$8
  Top 0.406: R11.2 94.2,90.15 R6.2
N$9
  Top 0.5: IC1.3 33.08,58.37 R19.1
  Top 0.6: R21.1 38,52.9 38,51 33,51 32.9,51.1 R22.2 32.9,58.35 R19.1
N$10
  Top 0.406: R8.2 84.8,80.1 R13.1 D3.A
N$11  (1 unrouted)
N$12
  Top 0.5: U1.7 40.4,34.7 37.2,31.3 37.79,30.81 2HDRV.2 2HDRV.3
N$13
  Top 0.5: 36.84,95.16 1HDRV.3 | 36.84,95.16 1HDRV.2 | U2.7 39.4,88.91 39.4,92.6 36.84,95.16 | 36.84,95.16
N$15
  Top 0.5: C17.1 R20.2 34.3,59.9 34.6,59.6 36.33,59.6 IC1.2 36.44,59.6 38.3,59.6 38.9,59 39,59 39,58 39.91,57.09 IC1.5
N$16
  Top 0.6: 36,44 D11.A | 36,44 35.6,44.4 2LODRV.3 | 36,44 36,44.2 35.9,43.97 2LODRV.2
  Top 1: 36,44.2 R18.2
N$18
  Top 0.5: IC1.6 43.64,58.37 44,58 46,58 R24.1 R23.2
N$20
  Top 0.5: D1.C 30.6,34 D5.K
N$23
  Top 0.5: R27.1 R9.2
N$24
  Top 0.5: D6.C 46.6,97.9 D7.K
N$29
  Top 0.406: R10.2 R29.2
  Top 0.5: R10.2 29.1,4.5 27,4.5 26.7,4.8 R12.E 23.79,5.46 R28.1 23,6
N$30
  Top 0.5: R9.1 18,5 21,9 22.55,9 R28.2 23,10 24.36,10.5 R12.A
N$31
  Top 0.4: 29.4,9.4 29.4,14.6 R7.2
  Top 0.5: R12.S 27.8,8.4 29.4,9.4
O_IFB  (via drill 0.51 pad 1.5)
  Top 0.254: 78.3,14 JP7.1
  Top 0.406: R24.2 45.1,61.1 43.9,59.7 41.67,59.7 IC1.7
  Top 1: v46,63 R24.2 46,62 | v78.3,16 78.3,14
  Bottom 0.5: v78.3,16 74.3,20 58,20 55,23 55,38 46,47 v46,63
PUMP+
  Top 0.254: P+2.1 91,73 91.38,73.27
  Top 0.406: P+1.1 94,75 95,76 95,83 94.65,84.35 R11.1 90.4,85.35 TRAFO.3
  Bottom 0.5: C1.+ 96,109 97,108 97,102 98,101 98,74 96,72 P+2.1
  pour Top (isolate 2, rank 2): 95,86 95,73 91,73 91,77 94,77 94,84.6 90,84.6 90,86
  pour Bottom (isolate 2, rank 3): -16,24 -16,8 7,8 7,14 24,14 27,16 27,103 40,103 40,113 44,113 45,112 45,109 50,109 50,112 64,112 64,108 65,107 70,107 70,112 86,112 89,109 89,107 105,107 105,121 16,121 13,111 6,111 6,118 -17,118 -17,102 5,102 5,107 14,107 19,112 29,112 29,108 22,108 20,105 20,21 18,19 6,19 6,24
  pour Top (isolate 2, rank 4): -16,24 -16,8 7,8 7,14 24,14 26,16 26,92 27,96 27,103 39,103 40,113 44,113 45,112 45,109 50,109 50,112 64,112 64,108 65,107 70,107 70,112 86,112 89,109 89,107 99,107 99,121 21,121 16,111 6,111 6,118 -17,118 -17,102 5,102 5,107 14,107 19,112 30,112 30,110 29,107 22,107 20,105 20,21 18,19 6,19 6,24
RED  (via drill 2.2 pad 3.81)  (2 unrouted)
  other vias: 12,30
  pour Bottom (isolate 2, rank 4): 2,49 13,48 13,45 8,45 6,43 6,34 18,34 18,24 11,20 10,20 9,21 2,27
  pour Top (isolate 2): 10,23 11,35 18,34 18,24 19,24 17,22 15,22 14,21 10,21
  pour Top (isolate 2, rank 3): 1,48 13,48 13,45 8,45 6,43 6,35 12,35 12,21 11,20 10,20 9,21 9,27 1,28
SCR2
  pour Top (isolate 2): 95,53 95,50 81,50 81,53
  pour Bottom (isolate 2): 95,53 95,50 81,50 81,53
SNUB1
  pour Top (isolate 2, rank 2): 79,53 79,41 72,41 72,53
  pour Bottom (isolate 2, rank 2): 79,53 79,41 72,41 72,53
SNUB2
  pour Top (isolate 2, rank 2): 79,37 79,25 72,25 72,37
  pour Bottom (isolate 2, rank 2): 79,37 79,25 72,25 72,37
SOURCE
  pour Top (isolate 2): 95,37 95,34 81,34 81,37
  pour Bottom (isolate 2): 95,37 95,34 81,34 81,37
TFB
  Top 0.5: NTC.1 38.63,10.33 40,12 40,12.78 JP7.16 40.22,14.22 41,15 41,16.8 C2.1
V12  (via drill 0.6, 0.6 pad 1.5)
  Top 0.254: 40,53 R21.2 | V12_2.1 82,72 82,73 82.17,73
  Top 0.406: C7.+ 88.45,77.45 87,76 84,76 V12_1.1 | V12_1.1 R13.2 | D9.K 80,78 V12_1.1 | v37,81 U2.1
  Top 0.5: 2LODRV.8 30.4,41.6 31,41 | 2LODRV.1 34.5,41 | 1LODRV.8 30.4,67.6 31,67 | 34.5,67 34.75,67.25 1LODRV.1 | C8.+ 53,19.05 U$2.3 51.3,15.3 50,14 50,13.38 JP7.12 50.3,12.92 v50.3,10.5
  Top 0.6: 1LODRV.1 35.69,68 | D8.A 48.4,31.5 U1.1 | v42,41 C16.1 | 36.69,41 2LODRV.1 | 41.69,61.7 IC1.8
  Top 1: v42,41 36.69,41 | v42,62.7 41.69,61.7 | v42,53 40,53 | v80,72 V12_2.1 | v50.8,30.6 50.85,30.55 C13.1 50,30.4 D8.A | 34.5,41 31,41 | 34.5,67 31,67 | 34.75,67.25 35,67 v42,67 41,68 C15.1
  Bottom 0.5: 50,17 50.1,17 50.3,16.8 v50.3,10.5 | v80,72 80,67 v42,67 | 46,35 46.08,34.3 49.68,30.6 | 49.68,30.6 49.79,30.49 49.79,28.21 50,28 | 49.68,30.6 v50.8,30.6
  Bottom 1: 46,35 46,39 v42,41 v42,53 v42,62.7 v42,67 42,74 v37,81 | 50,17 50,28
  pour Top (isolate 2): 89,79 89,73 80,73 80,78 87,78
  pour Top (isolate 1.5, rank 2): 34,83 36,83 37,82 38,82 38,80 34,80
VB1
  Top 0.406: D10.K 35,89 38.27,89 U2.8
  Top 0.5: 1HDRV.8 31,96.68 31,96 34,93 34,92 35.49,93.49 1HDRV.1
  pour Top (isolate 1.5, rank 2): 32,98 42,98 42,95 39,92 39,87 38,88 34,88 31,96
VB2
  Top 0.5: 2HDRV.8 35.82,25 36,25 33.95,22.95 C12.1 | 2HDRV.1 39.18,29 40,29 41,30 | 41,30 42,31 41.99,31.01 U1.8 | D8.K 42.4,31 41,30
  pour Top (isolate 1.5): 33,23 34,22 36,23 43,30 43,33 42,33 33,24
VDD
  Top 0.406: R26.1 46,20.4 46,17 46.35,17 U$2.1
  Top 0.5: VENT.2 45.3,9.57 | JP7.14 45.3,16.3 46,17 | C6.+ 43.7,20.9 44.1,20.5 44.9,20.5 R26.1
  Top 1: 45.3,9.57 JP7.14 | NTC.2 42.9,8.9 43,9 44.73,9 VENT.2
VFB
  Top 0.5: 31.1,17.1 33,19 38.5,19 | 38.5,19 43,19 43,13.24 | C10.1 38.3,19.2 38.5,19
  Top 0.8: R7.1 31.1,17.1 | 43,13.24 JP7.15
VREGM
  Top 0.5: R25.2 44.7,23.9 R26.2 47.6,22.6 48,23 48.35,23 U$2.4 U$2.2
  pour Top (isolate 1.016): 47,25 51,25 51,17 47,17 47,23
VS3
  Top 0.5: D1.A 25.3,31.51 ROUT6.1 | U1.6 39.06,36 38.1,35 37.4,34.4 36,34 36,33.19 2HDRV.4 35.18,33 35,33 | 32,28.82 2HDRV.5 | 32,28.82 32,29 | 32,28.82 31.82,29 31,29 29.45,27.45 C12.2
  pour Top (isolate 1.5): 25,32 26,32 29,29 30,29 36,35 42,35 42,34 38,34 31,27 28,26 25,29
VS4
  Top 0.5: 1HDRV.5 35.32,101 38,99 39,98 39,97 38.51,96.51 1HDRV.4 | U2.6 40.8,88.84 40.8,90.3 41.8,91.3 41.8,91.4
  pour Top (isolate 1.5): 25,108 29,108 39,98 43.9,97.8 44,93.6 41,88 40,95 34,101 33,101 29,105 26,105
